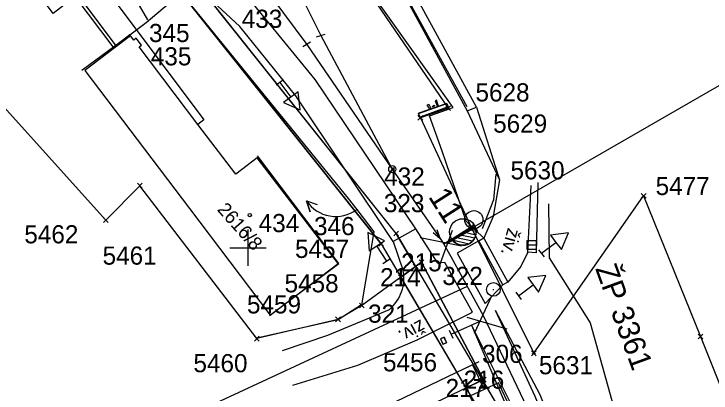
# Model space of a CAD drawing. Extents: x -804166 to -803706, y -1151030 to -1150147.
# Drawn here: x -803925.7 to -803849, y -1150516 to -1150474.2 of the extents above; entities that cross this region are included whole.
import ezdxf

# ---------------------------------------------------------------- set-up
doc = ezdxf.new("R2010")
doc.units = 0
for name, color, linetype in [('0381KM032-037P - Vrstva 1', 7, 'Continuous'), ('0381KM032-037P - Vrstva 12', 7, 'Continuous'), ('0381KM032-037P - Vrstva 13', 7, 'Continuous'), ('0381KM032-037P - Vrstva 17', 7, 'Continuous'), ('0381KM032-037P - Vrstva 19', 7, 'Continuous'), ('0381KM032-037P - Vrstva 2', 7, 'Continuous'), ('0381KM032-037P - Vrstva 23', 7, 'Continuous'), ('0381KM032-037P - Vrstva 4', 7, 'Continuous'), ('0381KM032-037P - Vrstva 43', 7, 'Continuous'), ('0381KM032-037P - Vrstva 49', 7, 'Continuous'), ('0381KM032-037P - Vrstva 5', 7, 'Continuous'), ('0381KM032-037P - Vrstva 51', 7, 'Continuous'), ('0381KM032-037P - Vrstva 55', 7, 'Continuous'), ('0381KM032-037P - Vrstva 57', 7, 'Continuous'), ('0381KM032-037P - Vrstva 59', 7, 'Continuous'), ('DZ - DZ_krizek', 7, 'Continuous'), ('DZ - DZ_ostat', 7, 'Continuous'), ('DZ - DZ_číslo', 7, 'Continuous'), ('DZ_CD - CD', 7, 'Continuous'), ('DZ_CD - CD_krizek', 7, 'Continuous'), ('DZ_CD - CD_čísla', 7, 'Continuous'), ('krizky_1000 - Vrstva 1', 7, 'Continuous'), ('szdc - hran DP', 7, 'Continuous'), ('szdc - szdc_cislo', 7, 'Continuous'), ('szdc - szdc_krizek', 7, 'Continuous'), ('VB - VB', 7, 'Continuous'), ('VB - VB_cislo', 7, 'Continuous'), ('VB - VB_krizek', 7, 'Continuous'), ('vyt_sit - stávající', 7, 'Continuous')]:
    doc.layers.add(name, color=color, linetype=linetype)

msp = doc.modelspace()

# ---------------------------------------------------------------- linework, layer by layer
at = {"layer": '0381KM032-037P - Vrstva 1'}
msp.add_line((-803901.897, -1150466.329), (-803893.522, -1150477.59), dxfattribs=at)
for points in [[(-804011.14, -1150262.39), (-804005.45, -1150273.41), (-803998.73, -1150284.85), (-803991.51, -1150295.63), (-803978.8, -1150312.77), (-803963.69, -1150332.99), (-803952.21, -1150348.36), (-803946.3, -1150356.39), (-803941.6, -1150363.14), (-803936.71, -1150370.83), (-803932.05, -1150378.84), (-803927.78, -1150386.91), (-803924.06, -1150395.18), (-803920.62, -1150403.65), (-803918.06, -1150410.86), (-803915.07, -1150420.32), (-803912.96, -1150427.25), (-803910.49, -1150435.34), (-803907.334, -1150445.05), (-803903.668, -1150454.381), (-803897.938, -1150464.596), (-803891.973, -1150476.598)], [(-803975.617, -1150392.296), (-803939.473, -1150444.116), (-803928.265, -1150459.416), (-803914.534, -1150477.731)], [(-803891.973, -1150476.598), (-803884.106, -1150491.333), (-803878.839, -1150498.97), (-803878.441, -1150499.601)], [(-803893.522, -1150477.59), (-803884.106, -1150491.333), (-803878.839, -1150498.97), (-803878.441, -1150499.601)], [(-803878.441, -1150499.601), (-803877.664, -1150500.946), (-803874.069, -1150507.541)], [(-803874.069, -1150507.541), (-803869.666, -1150516.774), (-803865.801, -1150526.594), (-803862.645, -1150536.71)]]:
    msp.add_lwpolyline(points, dxfattribs=at)
at = {"layer": '0381KM032-037P - Vrstva 12'}
for q in [(-803878.793, -1150510.039), (-803878.397, -1150509.87), (-803878.143, -1150510.457)]:
    msp.add_line((-803878.393, -1150509.855), q, dxfattribs=at)
for points in [[(-803878.788, -1150510.049), (-803878.793, -1150510.039), (-803878.537, -1150510.622), (-803878.523, -1150510.621)], [(-803878.397, -1150509.87), (-803878.788, -1150510.049), (-803878.523, -1150510.621), (-803878.141, -1150510.449), (-803878.397, -1150509.87)], [(-803878.537, -1150510.622), (-803878.143, -1150510.457), (-803878.141, -1150510.449)]]:
    msp.add_lwpolyline(points, dxfattribs=at)
at = {"layer": '0381KM032-037P - Vrstva 13'}
msp.add_lwpolyline([(-803875.883, -1150484.91), (-803874.859, -1150484.495), (-803883.662, -1150468.351), (-803886.496, -1150463.09), (-803890.342, -1150455.103), (-803892.739, -1150449.637), (-803894.892, -1150444.207), (-803895.921, -1150441.276), (-803896.676, -1150438.635), (-803897.147, -1150435.872), (-803897.2, -1150433.432), (-803898.654, -1150433.258), (-803898.54, -1150435.86), (-803897.995, -1150438.863), (-803897.041, -1150441.738), (-803895.987, -1150444.528), (-803893.704, -1150450.064), (-803891.289, -1150455.545), (-803887.412, -1150463.602)], close=True, dxfattribs=at)
at = {"layer": '0381KM032-037P - Vrstva 17'}
for p, q in [((-803911.209, -1150475.173), (-803907.336, -1150471.899)), ((-803888.961, -1150494.568), (-803888.027, -1150495.776))]:
    msp.add_line(p, q, dxfattribs=at)
for points in [[(-803875.87, -1150484.459), (-803884.486, -1150468.8), (-803887.25, -1150463.566), (-803891.192, -1150455.528), (-803893.615, -1150450.032), (-803895.787, -1150444.436), (-803896.9, -1150441.761), (-803897.818, -1150438.885), (-803898.314, -1150435.883), (-803898.256, -1150432.783)], [(-803907.336, -1150471.899), (-803888.961, -1150494.568)], [(-803912.992, -1150476.532), (-803911.209, -1150475.173)], [(-803872.719, -1150491.9), (-803872.971, -1150494.735), (-803874.21, -1150497.92)], [(-803888.027, -1150495.776), (-803886.131, -1150498.244), (-803887.49, -1150506.275), (-803890.053, -1150507.927), (-803899.02, -1150509.954)]]:
    msp.add_lwpolyline(points, dxfattribs=at)
at = {"layer": '0381KM032-037P - Vrstva 19'}
for p, q in [((-803879.404, -1150483.821), (-803879.155, -1150484.356)), ((-803881.212, -1150485.202), (-803878.118, -1150484.104)), ((-803877.97, -1150484.474), (-803881.045, -1150485.616)), ((-803879.155, -1150484.356), (-803879.022, -1150484.392)), ((-803878.118, -1150484.104), (-803877.97, -1150484.474)), ((-803881.045, -1150485.616), (-803881.212, -1150485.202))]:
    msp.add_line(p, q, dxfattribs=at)
for points in [[(-803879.022, -1150484.392), (-803879.242, -1150483.752), (-803879.404, -1150483.821)], [(-803878.118, -1150484.104), (-803878.118, -1150484.104), (-803881.188, -1150485.171), (-803881.212, -1150485.202)], [(-803880.088, -1150484.181), (-803879.836, -1150484.689), (-803880.019, -1150484.664), (-803880.278, -1150484.296), (-803880.088, -1150484.181)]]:
    msp.add_lwpolyline(points, dxfattribs=at)
msp.add_ellipse((-803879.582, -1150484.395), major_axis=(-0.127, -0.08), ratio=0.380929, dxfattribs=at)
at = {"layer": '0381KM032-037P - Vrstva 2'}
for p, q in [((-803878.441, -1150499.601), (-803834.824, -1150474.404)), ((-803892.452, -1150476.741), (-803891.494, -1150476.455)), ((-803891.973, -1150476.598), (-803884.106, -1150491.333)), ((-803893.094, -1150477.331), (-803893.95, -1150477.849)), ((-803877.575, -1150499.045), (-803875.106, -1150497.473)), ((-803875.427, -1150497.677), (-803874.961, -1150497.78)), ((-803876.77, -1150498.532), (-803875.035, -1150498.916)), ((-803876.321, -1150498.247), (-803874.912, -1150498.559)), ((-803875.874, -1150497.962), (-803874.883, -1150498.182)), ((-803877.576, -1150499.046), (-803878.441, -1150499.601)), ((-803877.574, -1150499.046), (-803877.575, -1150499.045)), ((-803877.507, -1150499.136), (-803875.654, -1150499.547)), ((-803877.217, -1150498.817), (-803875.266, -1150499.249))]:
    msp.add_line(p, q, dxfattribs=at)
for points in [[(-803893.522, -1150477.59), (-803884.106, -1150491.333), (-803878.839, -1150498.97), (-803878.441, -1150499.601)], [(-803879.6, -1150498.322), (-803878.839, -1150498.97), (-803879.174, -1150498.028)]]:
    msp.add_lwpolyline(points, dxfattribs=at)
for centre, radius in [((-803884.106, -1150491.333), 0.4), ((-803876.333, -1150498.256), 1.462)]:
    msp.add_circle(centre, radius, dxfattribs=at)
msp.add_arc((-803876.341, -1150498.259), 1.464, 212.53717, 32.49802, dxfattribs=at)
at = {"layer": '0381KM032-037P - Vrstva 23'}
for p, q in [((-803893.152, -1150496.036), (-803893.533, -1150494.83)), ((-803893.533, -1150494.83), (-803893.152, -1150496.036)), ((-803893.533, -1150494.83), (-803892.379, -1150495.228))]:
    msp.add_line(p, q, dxfattribs=at)
for points in [[(-803912.992, -1150476.532), (-803913.943, -1150477.255), (-803918.261, -1150480.471)], [(-803897.633, -1150507.469), (-803890, -1150501.72), (-803898.947, -1150489.885)]]:
    msp.add_lwpolyline(points, dxfattribs=at)
msp.add_arc((-803890.335, -1150492.714), 3.834, 213.48969, 307.00957, dxfattribs=at)
at = {"layer": '0381KM032-037P - Vrstva 4'}
for p, q in [((-803874.948, -1150497.783), (-803877.999, -1150499.498)), ((-803874.703, -1150498.219), (-803875.193, -1150497.347)), ((-803879.067, -1150502.394), (-803877.487, -1150498.063)), ((-803876.506, -1150499.806), (-803881.027, -1150498.907)), ((-803877.664, -1150500.946), (-803874.069, -1150507.541)), ((-803875.88, -1150504.253), (-803939.777, -1150533.943)), ((-803873.145, -1150505.275), (-803875.086, -1150509.456)), ((-803875.915, -1150507.636), (-803871.486, -1150508.915)), ((-803877.639, -1150509.52), (-803874.454, -1150508.069)), ((-803877.846, -1150509.065), (-803877.432, -1150509.975))]:
    msp.add_line(p, q, dxfattribs=at)
for points in [[(-803872.779, -1150506.875), (-803867.872, -1150516.171), (-803864.004, -1150525.679), (-803860.599, -1150536.286), (-803857.956, -1150547.888), (-803856.113, -1150558.65), (-803855.009, -1150569.422), (-803855.013, -1150580.14), (-803855.681, -1150591.137), (-803857.109, -1150602.102)], [(-803872.779, -1150506.875), (-803868.424, -1150516.34), (-803864.491, -1150525.922), (-803861.191, -1150536.397), (-803858.415, -1150547.949), (-803856.721, -1150558.765), (-803855.706, -1150569.464), (-803855.706, -1150580.041), (-803856.439, -1150591.045), (-803858.016, -1150602.009)], [(-803875.392, -1150508.511), (-803870.942, -1150517.43), (-803867.281, -1150527.019), (-803864.067, -1150537.143), (-803861.546, -1150548.304), (-803859.948, -1150558.943), (-803859.253, -1150569.653), (-803859.085, -1150579.867)], [(-803875.392, -1150508.511), (-803871.454, -1150517.68), (-803867.834, -1150527.236), (-803864.663, -1150537.291), (-803862.152, -1150548.382), (-803860.595, -1150558.999), (-803859.922, -1150569.628), (-803859.947, -1150579.801), (-803860.5, -1150590.58), (-803862.041, -1150601.171)]]:
    msp.add_lwpolyline(points, dxfattribs=at)
at = {"layer": '0381KM032-037P - Vrstva 43'}
for points in [[(-803871.406, -1150503.772), (-803871.943, -1150504.067), (-803874.575, -1150499.234), (-803874.041, -1150498.946), (-803871.406, -1150503.772)], [(-803874.573, -1150499.229), (-803874.026, -1150498.951), (-803871.394, -1150503.78), (-803871.938, -1150504.086), (-803874.573, -1150499.229)], [(-803869.26, -1150499.687), (-803869.26, -1150499.187), (-803868.26, -1150499.187), (-803868.26, -1150500.187), (-803869.26, -1150500.187), (-803869.26, -1150499.687), (-803868.26, -1150499.687)]]:
    msp.add_lwpolyline(points, dxfattribs=at)
msp.add_circle((-803875.129, -1150496.91), 1, dxfattribs=at)
at = {"layer": '0381KM032-037P - Vrstva 49'}
for p, q in [((-803880.011, -1150485.455), (-803877.416, -1150484.532)), ((-803875.883, -1150484.91), (-803872.322, -1150492.497)), ((-803868.71, -1150511.374), (-803868.356, -1150511.726)), ((-803868.357, -1150511.373), (-803868.709, -1150511.727)), ((-803874.253, -1150514.268), (-803873.899, -1150514.62)), ((-803873.9, -1150514.267), (-803874.252, -1150514.621))]:
    msp.add_line(p, q, dxfattribs=at)
for points in [[(-803920.94, -1150376.21), (-803910.018, -1150390.511), (-803912.553, -1150396.059), (-803903.866, -1150412.95), (-803903.684, -1150418.644), (-803901.421, -1150428.97), (-803900.537, -1150437.639), (-803895.89, -1150448.56), (-803892.01, -1150457.3), (-803887.412, -1150463.602), (-803875.883, -1150484.91), (-803874.859, -1150484.495), (-803872.322, -1150492.497), (-803872.997, -1150496.546), (-803874.041, -1150498.946)], [(-803877.416, -1150484.532), (-803894.615, -1150460.334), (-803907.648, -1150433.624), (-803908.812, -1150430.908)], [(-803874.041, -1150498.946), (-803875.993, -1150497.05), (-803878.613, -1150489.357), (-803880.011, -1150485.455)], [(-803866.91, -1150495.141), (-803866.848, -1150501.095), (-803862.336, -1150508.281), (-803859.067, -1150519.976)]]:
    msp.add_lwpolyline(points, dxfattribs=at)
at = {"layer": '0381KM032-037P - Vrstva 5'}
for p, q in [((-803875.265, -1150512.897), (-803915.956, -1150532.369)), ((-803874.586, -1150512.578), (-803875.944, -1150513.216))]:
    msp.add_line(p, q, dxfattribs=at)
msp.add_lwpolyline([(-803875.265, -1150512.897), (-803873.991, -1150515.613), (-803875.575, -1150516.356), (-803874.513, -1150518.62), (-803871.345, -1150517.133), (-803872.407, -1150514.87), (-803873.991, -1150515.613)], dxfattribs=at)
at = {"layer": '0381KM032-037P - Vrstva 51'}
for p, q in [((-803915.449, -1150467.279), (-803911.051, -1150474.867)), ((-803900.893, -1150475.608), (-803905.683, -1150471.142)), ((-803896.066, -1150481.493), (-803896.874, -1150482.083)), ((-803881.519, -1150497.913), (-803884.008, -1150499.305)), ((-803879.108, -1150501.711), (-803881.519, -1150497.913)), ((-803884.008, -1150499.305), (-803882.935, -1150502.416)), ((-803868.005, -1150500.208), (-803867.403, -1150501.008)), ((-803885.131, -1150501.736), (-803884.297, -1150501.184)), ((-803870.52, -1150504.875), (-803869.928, -1150505.681))]:
    msp.add_line(p, q, dxfattribs=at)
for points in [[(-803881.519, -1150497.913), (-803892.597, -1150481.46), (-803901.351, -1150470.694), (-803906.021, -1150467.127), (-803910.842, -1150463.746), (-803913.43, -1150460.674), (-803913.908, -1150457.138), (-803915.72, -1150453.288)], [(-803884.008, -1150499.305), (-803894.736, -1150483.244), (-803900.893, -1150475.608)], [(-803896.47, -1150481.788), (-803895.29, -1150483.403), (-803896.098, -1150483.993), (-803894.258, -1150484.816), (-803894.483, -1150482.813), (-803895.29, -1150483.403)], [(-803872.322, -1150492.497), (-803872.997, -1150496.546), (-803874.041, -1150498.946), (-803874.575, -1150499.234), (-803876.979, -1150500.591), (-803873.894, -1150506.131)], [(-803868.09, -1150492.82), (-803868.275, -1150500.556), (-803869.181, -1150500.495), (-803868.824, -1150493.135)], [(-803884.714, -1150501.46), (-803885.817, -1150499.792), (-803884.983, -1150499.24), (-803886.783, -1150498.332), (-803886.651, -1150500.344), (-803885.817, -1150499.792)], [(-803867.704, -1150500.608), (-803866.106, -1150499.406), (-803865.505, -1150500.205), (-803864.707, -1150498.354), (-803866.707, -1150498.607), (-803866.106, -1150499.406)], [(-803869.181, -1150500.495), (-803869.951, -1150502.075), (-803871.406, -1150503.772), (-803871.943, -1150504.067), (-803873.894, -1150506.131)], [(-803875.265, -1150507.099), (-803878.317, -1150501.626), (-803879.108, -1150501.711)], [(-803870.224, -1150505.278), (-803868.612, -1150504.094), (-803868.02, -1150504.899), (-803867.202, -1150503.057), (-803869.205, -1150503.288), (-803868.612, -1150504.094)], [(-803884.454, -1150506.841), (-803891.238, -1150509.65), (-803896.223, -1150511.347)], [(-803895.065, -1150515.152), (-803887.917, -1150512.923), (-803881.363, -1150510.148), (-803875.265, -1150507.099)]]:
    msp.add_lwpolyline(points, dxfattribs=at)
msp.add_ellipse((-803887.406, -1150503.348), major_axis=(0.394, 4.563), ratio=0.996998, start_param=3.930903, end_param=5.00319, dxfattribs=at)
at = {"layer": '0381KM032-037P - Vrstva 55'}
for points in [[(-803914.71, -1150478.01), (-803919.01, -1150472.26), (-803921.41, -1150474.2), (-803924.33, -1150470.27), (-803930.11, -1150474.6), (-803931.57, -1150472.66), (-803925.79, -1150468.33), (-803920.83, -1150464.56), (-803917.63, -1150468.64), (-803916.3, -1150467.69), (-803915.12, -1150469.35), (-803916.46, -1150470.34), (-803904.84, -1150485.91), (-803905.5, -1150486.41)], [(-803901.34, -1150491.89), (-803905.5, -1150486.41), (-803911.98, -1150477.87), (-803911.71, -1150477.67), (-803912.3, -1150476.91), (-803912.56, -1150477.11), (-803912.92, -1150476.64), (-803914.71, -1150478.01), (-803917.95, -1150480.48), (-803906.42, -1150495.69), (-803897.53, -1150507.41), (-803890.06, -1150501.75), (-803898.96, -1150490.08), (-803901.34, -1150491.89)]]:
    msp.add_lwpolyline(points, dxfattribs=at)
at = {"layer": '0381KM032-037P - Vrstva 59'}
msp.add_circle((-803899.791, -1150496.398), 0.175, dxfattribs=at)
at = {"layer": 'DZ - DZ_krizek'}
for p, q in [((-803880.635, -1150501.865), (-803881.166, -1150501.335)), ((-803881.166, -1150501.865), (-803880.635, -1150501.335)), ((-803882.905, -1150503.508), (-803883.436, -1150502.978)), ((-803883.436, -1150503.508), (-803882.905, -1150502.978)), ((-803873.795, -1150514.795), (-803874.326, -1150514.265)), ((-803874.326, -1150514.795), (-803873.795, -1150514.265)), ((-803875.731, -1150515.713), (-803876.262, -1150515.183)), ((-803876.262, -1150515.713), (-803875.731, -1150515.183))]:
    msp.add_line(p, q, dxfattribs=at)
at = {"layer": 'DZ - DZ_ostat'}
for p, q in [((-803883.17, -1150503.243), (-803880.9, -1150501.6)), ((-803880.9, -1150501.6), (-803874.06, -1150514.53)), ((-803875.996, -1150515.448), (-803883.17, -1150503.243)), ((-803874.06, -1150514.53), (-803875.996, -1150515.448))]:
    msp.add_line(p, q, dxfattribs=at)
at = {"layer": 'DZ_CD - CD'}
for p, q in [((-803883.675, -1150498.437), (-803904.526, -1150472.225)), ((-803906.72, -1150472.679), (-803885.328, -1150499.572)), ((-803881.542, -1150502.065), (-803883.675, -1150498.437)), ((-803885.328, -1150499.572), (-803883.17, -1150503.243)), ((-803883.17, -1150503.243), (-803881.542, -1150502.065)), ((-803875.996, -1150515.448), (-803874.182, -1150514.588)), ((-803874.182, -1150514.588), (-803869.623, -1150522.344)), ((-803871.427, -1150523.222), (-803875.996, -1150515.448))]:
    msp.add_line(p, q, dxfattribs=at)
at = {"layer": 'DZ_CD - CD_krizek'}
for p, q in [((-803883.41, -1150498.702), (-803883.941, -1150498.172)), ((-803883.941, -1150498.702), (-803883.41, -1150498.172)), ((-803885.063, -1150499.837), (-803885.594, -1150499.307)), ((-803885.594, -1150499.837), (-803885.063, -1150499.307)), ((-803881.277, -1150502.33), (-803881.808, -1150501.8)), ((-803881.808, -1150502.33), (-803881.277, -1150501.8)), ((-803882.905, -1150503.508), (-803883.436, -1150502.978)), ((-803883.436, -1150503.508), (-803882.905, -1150502.978)), ((-803873.917, -1150514.853), (-803874.448, -1150514.323)), ((-803874.448, -1150514.853), (-803873.917, -1150514.323)), ((-803875.731, -1150515.713), (-803876.262, -1150515.183)), ((-803876.262, -1150515.713), (-803875.731, -1150515.183))]:
    msp.add_line(p, q, dxfattribs=at)
at = {"layer": 'krizky_1000 - Vrstva 1'}
for points in [[(-803900, -1150498), (-803900, -1150502)], [(-803902, -1150500), (-803898, -1150500)]]:
    msp.add_lwpolyline(points, dxfattribs=at)
at = {"layer": 'szdc - hran DP'}
for p, q in [((-803893.94, -1150461.19), (-803877.95, -1150484.62)), ((-803915.62, -1150496.95), (-803930.65, -1150480.27)), ((-803877.95, -1150484.62), (-803881.02, -1150485.69)), ((-803881.02, -1150485.69), (-803875.42, -1150497.74)), ((-803911.88, -1150493.16), (-803915.62, -1150496.95)), ((-803899.02, -1150510.01), (-803911.88, -1150493.16)), ((-803868.53, -1150511.63), (-803856.45, -1150494.27)), ((-803856.45, -1150494.27), (-803850.2, -1150509.77)), ((-803875.42, -1150497.74), (-803868.53, -1150511.63)), ((-803880.9, -1150501.6), (-803887.46, -1150506.35)), ((-803874.06, -1150514.53), (-803880.9, -1150501.6)), ((-803887.46, -1150506.35), (-803890.08, -1150507.89)), ((-803890.08, -1150507.89), (-803899.02, -1150510.01)), ((-803850.2, -1150509.77), (-803847.85, -1150515.64)), ((-803881.88, -1150518.24), (-803874.06, -1150514.53))]:
    msp.add_line(p, q, dxfattribs=at)
at = {"layer": 'szdc - szdc_krizek'}
for p, q in [((-803877.685, -1150484.885), (-803878.216, -1150484.355)), ((-803878.216, -1150484.885), (-803877.685, -1150484.355)), ((-803880.755, -1150485.955), (-803881.286, -1150485.425)), ((-803881.286, -1150485.955), (-803880.755, -1150485.425)), ((-803911.615, -1150493.425), (-803912.146, -1150492.895)), ((-803912.146, -1150493.425), (-803911.615, -1150492.895)), ((-803856.185, -1150494.535), (-803856.716, -1150494.005)), ((-803856.716, -1150494.535), (-803856.185, -1150494.005)), ((-803915.355, -1150497.215), (-803915.886, -1150496.685)), ((-803915.886, -1150497.215), (-803915.355, -1150496.685)), ((-803875.155, -1150498.005), (-803875.686, -1150497.475)), ((-803875.686, -1150498.005), (-803875.155, -1150497.475)), ((-803880.635, -1150501.865), (-803881.166, -1150501.335)), ((-803881.166, -1150501.865), (-803880.635, -1150501.335)), ((-803887.195, -1150506.615), (-803887.726, -1150506.085)), ((-803887.726, -1150506.615), (-803887.195, -1150506.085)), ((-803889.815, -1150508.155), (-803890.346, -1150507.625)), ((-803890.346, -1150508.155), (-803889.815, -1150507.625)), ((-803898.755, -1150510.275), (-803899.286, -1150509.745)), ((-803899.286, -1150510.275), (-803898.755, -1150509.745)), ((-803849.935, -1150510.035), (-803850.466, -1150509.505)), ((-803850.466, -1150510.035), (-803849.935, -1150509.505)), ((-803868.265, -1150511.895), (-803868.796, -1150511.365)), ((-803868.796, -1150511.895), (-803868.265, -1150511.365)), ((-803873.795, -1150514.795), (-803874.326, -1150514.265)), ((-803874.326, -1150514.795), (-803873.795, -1150514.265))]:
    msp.add_line(p, q, dxfattribs=at)
at = {"layer": 'VB - VB'}
for p, q in [((-803883.675, -1150498.437), (-803869.623, -1150522.344)), ((-803885.328, -1150499.572), (-803871.427, -1150523.222))]:
    msp.add_line(p, q, dxfattribs=at)
for points in [[(-803883.675, -1150498.437), (-803904.526, -1150472.225), (-803903.322, -1150467.763)], [(-803885.328, -1150499.572), (-803906.72, -1150472.679), (-803905.507, -1150468.183)]]:
    msp.add_lwpolyline(points, dxfattribs=at)
at = {"layer": 'VB - VB_krizek'}
for p, q in [((-803883.41, -1150498.702), (-803883.941, -1150498.172)), ((-803883.941, -1150498.702), (-803883.41, -1150498.172)), ((-803885.063, -1150499.837), (-803885.594, -1150499.307)), ((-803885.594, -1150499.837), (-803885.063, -1150499.307))]:
    msp.add_line(p, q, dxfattribs=at)
at = {"layer": 'vyt_sit - stávající'}
msp.add_line((-803873.031, -1150504.591), (-803872.931, -1150504.591), dxfattribs=at)
msp.add_circle((-803872.981, -1150504.591), 0.756, dxfattribs=at)

# ---------------------------------------------------------------- texts
at = {"layer": '0381KM032-037P - Vrstva 2'}
msp.add_text('11', height=2.5, rotation=302.51759, dxfattribs=at).set_placement((-803880.207, -1150494.369))
at = {"layer": '0381KM032-037P - Vrstva 51'}
for rotation, p in [(254.39036, (-803871.378, -1150497.731)), (207.94807, (-803880.962, -1150507.851))]:
    msp.add_text('živ.', height=1.5, rotation=rotation, dxfattribs=at).set_placement(p)
at = {"layer": '0381KM032-037P - Vrstva 57'}
msp.add_text('2616/8', height=1.5, rotation=311.46226, dxfattribs=at).set_placement((-803903.451, -1150495.836))
at = {"layer": 'DZ - DZ_číslo'}
for s, p in [('215', (-803883.136, -1150502.6)), ('214', (-803885.453, -1150504.243)), ('216', (-803876.249, -1150515.53)), ('217', (-803878.24, -1150516.448))]:
    msp.add_text(s, height=2, dxfattribs=at).set_placement(p)
at = {"layer": 'DZ_CD - CD_čísla'}
for s, p in [('345', (-803910.88, -1150477.333)), ('323', (-803885.036, -1150496.077)), ('346', (-803892.718, -1150498.609)), ('322', (-803878.609, -1150504.1)), ('321', (-803886.771, -1150508.255)), ('306', (-803874.233, -1150512.686))]:
    msp.add_text(s, height=2, dxfattribs=at).set_placement(p)
at = {"layer": 'szdc - szdc_cislo'}
for s, p in [('5628', (-803874.953, -1150483.877)), ('5629', (-803873.012, -1150487.313)), ('5630', (-803871.102, -1150492.466)), ('5477', (-803855.131, -1150494.192)), ('5462', (-803924.601, -1150499.512)), ('5457', (-803894.813, -1150501.119)), ('5461', (-803915.987, -1150501.86)), ('5458', (-803895.966, -1150504.91)), ('5459', (-803900.101, -1150507.234)), ('5456', (-803885.131, -1150513.613)), ('5460', (-803905.99, -1150513.714)), ('5631', (-803867.974, -1150513.937))]:
    msp.add_text(s, height=2, dxfattribs=at).set_placement(p)
at = {"layer": 'VB - VB_cislo'}
for s, p in [('433', (-803900.674, -1150475.769)), ('435', (-803910.681, -1150479.902)), ('432', (-803884.998, -1150493.146)), ('434', (-803898.812, -1150498.275))]:
    msp.add_text(s, height=2, dxfattribs=at).set_placement(p)
at = {"layer": 'vyt_sit - stávající'}
msp.add_text('ŽP 3361', height=2.4, rotation=290, dxfattribs=at).set_placement((-803861.801, -1150502.287))

doc.saveas('drawing.dxf')
